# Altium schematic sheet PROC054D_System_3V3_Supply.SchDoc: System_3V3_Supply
size 558 x 431 mm; Date: Not shown in title block; ApprovedBy: Not shown in title block; CheckedBy: Not shown in title block; Author: Not shown in title block; CompanyName: Not shown in title block; DrawnBy: a0271760; Engineer: Not shown in title block; Organization: Not shown in title block; Address1: Not shown in title block; Address2: Not shown in title block; Address3: Not shown in title block; Address4: Not shown in title block; DocumentNumber: 8; Revision: Use project pAWRameter SCH_Rev; SheetNumber: 8; SheetTotal: 19; PageSetup: Record=PageOptions¦CenterHorizontal=True¦CenterVertical=True¦PrintScale=1.00¦XCorrection=1.00¦YCorrection=1.00¦PrintKind=0¦BorderSize=5000000¦LeftOffset=0¦BottomOffset=0¦Orientation=2¦PaperLength=1000¦PaperWidth=1000¦Scale=100¦PaperSource=15¦PrintQuality=600¦MediaType=1¦DitherType=10¦PaperKind=Letter¦PrintScaleMode=1
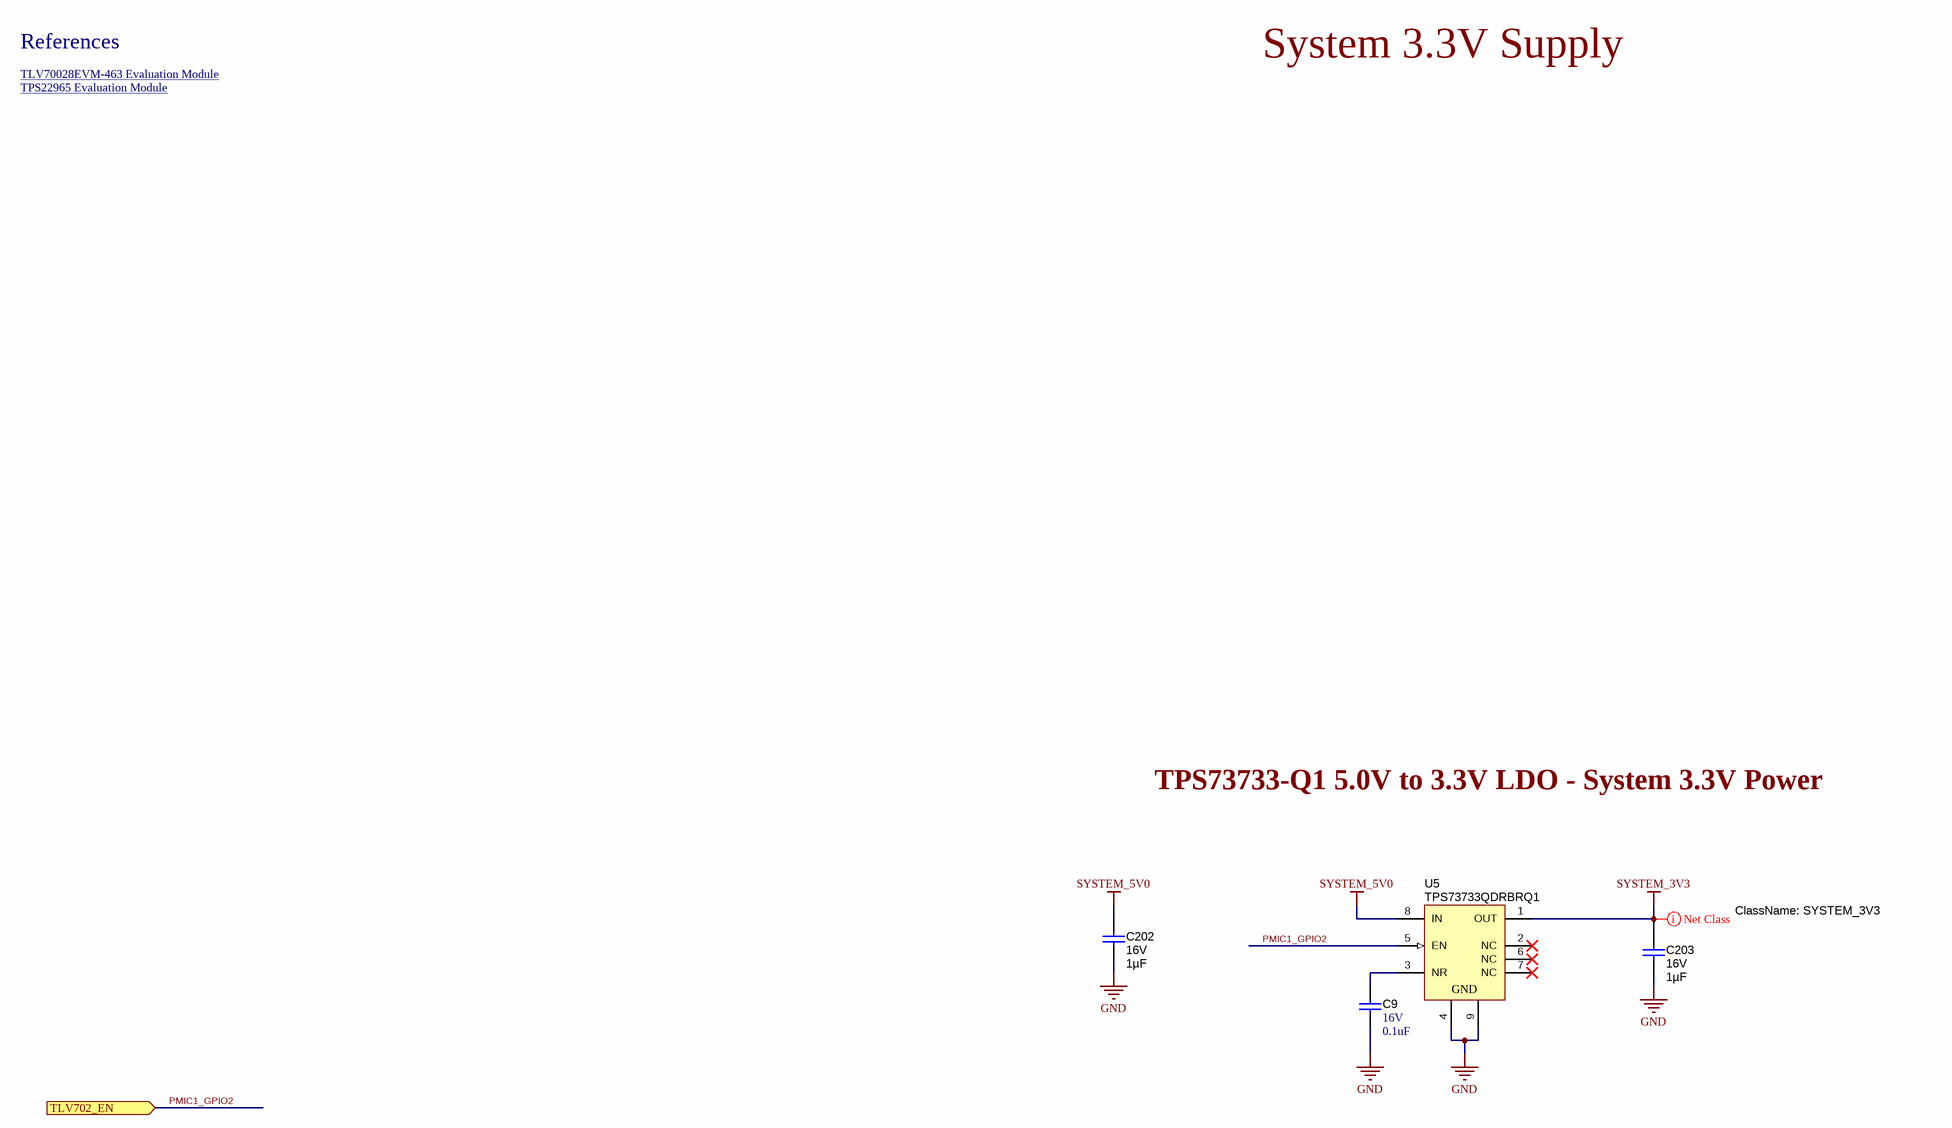
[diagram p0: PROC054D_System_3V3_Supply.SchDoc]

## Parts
C9  VDC_V: 16V  ValueDisplayed: 0.1uF  [0402]  (hidden comment: GCM155R71C104KA55D)
C202  VDC_V: 16V  ValueDisplayed: 1µF  [0603]  (hidden comment: GCM188R71C105KA64J)
C203  VDC_V: 16V  ValueDisplayed: 1µF  [0603]  (hidden comment: GCM188R71C105KA64J)
U5  TPS73733QDRBRQ1  [DRB0008A]

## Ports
TLV702_EN (in)

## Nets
GND: C9.2 C202.2 C203.2 U5.4(GND) U5.9(GND)
SYSTEM_3V3: C203.1 U5.1(OUT)
SYSTEM_5V0: C202.1 U5.8(IN)
PMIC1_GPIO2: U5.5(EN) ; port TLV702_EN
NetC9_1: C9.1 U5.3(NR)

Not connected (* = marked no-connect by the designer): U5 2(NC)* 6(NC)* 7(NC)*

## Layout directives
net class SYSTEM_3V3: SYSTEM_3V3

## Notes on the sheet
- References
- System 3.3V Supply
- TLV70028EVM-463 Evaluation Module <http://www.ti.com/tool/tlv70028evm-463>
- TPS22965 Evaluation Module <http://www.ti.com/tool/tps22965evm-023>
- TPS73733-Q1 5.0V to 3.3V LDO - System 3.3V Power

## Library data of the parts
C9 = CMP-0006351-2: CAP, CERM, 0.1 uF, 16 V, +/- 10%, X7R, 0402; Manufacturer: MuRata; TaMin_C: -55°C; Polarized: N; SizeAreaWB_mm2: 3; Value1: Unknown; U/M: EA; Value: 0.1uF; TaMax_C: 125°C; SizeZ_mm: 0.6; SizeX_mm: 1; SizeY_mm: 0.5; Cap_F: 100nF; AEC Category: Q200
C202 C203 = CMP-0079154-1: CAP, CERM, 1 µF, 16 V,+/- 10%, X7R, AEC-Q200 Grade 1, 0603; Manufacturer: MuRata; SizeAreaWB_mm2: 4.68; SizeArea_mm2: 1.28; AEC Qualified: Y; AEC Category: Q200; Value: 1uF; TaMax_C: 125°C; SizeZ_mm: 1; Polarized: N; TaMin_C: -55°C; SizeY_mm: 0.8; U/M: EA; SizeX_mm: 1.6
U5 = CMP-0036354-2: Single Output Automotive LDO, 1 A, Fixed 3.3 V Output, 2.2 to 5.5 V Input, with Reverse Current Protection, 8-pin SON (DRB), -40 to 125 degC, Green (RoHS & no Sb/Br); Manufacturer: Texas Instruments; Vin(Min)(V): 2.2; Vout Adj(Max)(V): 3.3; Vin(Max)(V): 5.5; Accuracy(%): 3; SubFamily: Single Channel LDO; Iq(Typ)(mA): 0.3; Vdo(Typ)(mV): 130; Iout(Max)(A): 1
